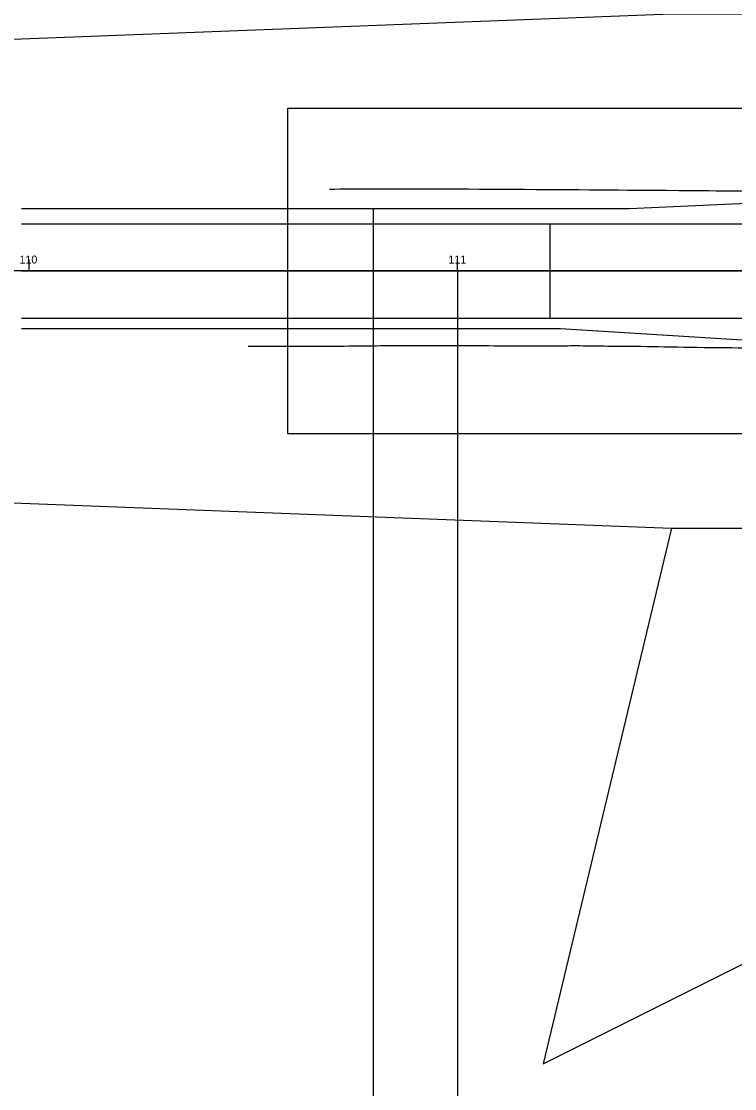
# Model space of a CAD drawing. Extents: x -1300 to 1299, y -770 to 1120.
# Drawn here: x 391.5 to 558, y 234.1 to 483.1 of the extents above; entities that cross this region are included whole.
import ezdxf

# ---------------------------------------------------------------- set-up
doc = ezdxf.new("R2010")
doc.units = 0
for name, color, linetype in [('GE_X_CL_20', 7, 'Continuous'), ('MD_P_CONST_LIMITS', 7, 'Continuous'), ('PM_P_CL_Dashed', 7, 'Continuous'), ('PM_X_CL_Dashed', 7, 'Continuous'), ('PM_X_Edge_Line', 7, 'Continuous'), ('PV_P_Shoulder_Rumble_Strip', 7, 'Continuous'), ('PV_X_EOP', 7, 'Continuous'), ('RD_X_GR_Lt', 7, 'Continuous'), ('RD_X_GR_Rt', 7, 'Continuous'), ('RW_X_Esmt_CH', 7, 'Continuous'), ('RW_X_Fee_RW', 7, 'Continuous'), ('SC_Scratch1', 7, 'Continuous'), ('SC_Scratch2', 7, 'Continuous')]:
    doc.layers.add(name, color=color, linetype=linetype)

msp = doc.modelspace()

# ---------------------------------------------------------------- linework, layer by layer
at = {"layer": 'GE_X_CL_20'}
for p, q in [((393.26, 424.91), (393.26, 426.24)), ((493.26, 424.91), (493.26, 426.24)), ((391.46, 424.91), (920.48, 424.91))]:
    msp.add_line(p, q, dxfattribs=at)
at = {"layer": 'MD_P_CONST_LIMITS'}
msp.add_lwpolyline([(453.64, 462.91), (867.88, 462.91), (867.88, 386.91), (453.64, 386.91)], close=True, dxfattribs=at)
at = {"layer": 'PM_P_CL_Dashed'}
msp.add_line((473.64, 424.91), (847.88, 424.91), dxfattribs=at)
at = {"layer": 'PM_X_CL_Dashed'}
msp.add_line((473.64, 424.91), (151.14, 424.91), dxfattribs=at)
at = {"layer": 'PM_X_Edge_Line'}
for p, q in [((391.46, 435.91), (920.48, 435.91)), ((391.46, 413.91), (920.48, 413.91))]:
    msp.add_line(p, q, dxfattribs=at)
at = {"layer": 'PV_P_Shoulder_Rumble_Strip'}
msp.add_line((611.14, 424.91), (193.26, 424.91), dxfattribs=at)
at = {"layer": 'PV_X_EOP'}
for points in [[(621.54, 442.91), (610.47, 442.91), (533.45, 439.41), (391.46, 439.41)], [(600.75, 406.91), (589.69, 406.91), (517.28, 411.41), (391.46, 411.41)]]:
    msp.add_lwpolyline(points, dxfattribs=at)
at = {"layer": 'RD_X_GR_Lt'}
msp.add_open_spline([(596, 406.91), (587.6, 406.9), (581.57, 406.91), (574.81, 406.91), (569.65, 406.78), (559.34, 406.93), (545.66, 407.05), (534.45, 407.31), (526.08, 407.31), (520.46, 407.46), (514.42, 407.28), (505.23, 407.39), (481.4, 407.51), (469.35, 407.3), (451.19, 407.23), (444.37, 407.31)], degree=3, dxfattribs=at)
at = {"layer": 'RD_X_GR_Rt'}
msp.add_open_spline([(616.46, 442.92), (603.16, 442.96), (595.89, 442.89), (588.44, 443.03), (575.12, 443.26), (561.63, 443.48), (552.94, 443.56), (475.29, 444.16), (463.39, 443.93)], degree=3, dxfattribs=at)
at = {"layer": 'RW_X_Esmt_CH'}
msp.add_lwpolyline([(543.26, 364.91), (513.26, 239.91), (593.26, 279.91), (698.26, 364.91)], dxfattribs=at)
at = {"layer": 'RW_X_Fee_RW'}
for points in [[(193.26, 471.45), (543.26, 484.91), (763.26, 484.91), (1043.26, 474.91)], [(193.26, 378.37), (543.26, 364.91), (763.26, 364.91), (1043.26, 379.91)]]:
    msp.add_lwpolyline(points, dxfattribs=at)
at = {"layer": 'SC_Scratch1'}
for p, q in [((473.64, -369.36), (473.64, 439.41)), ((514.91, 424.91), (514.91, 435.91)), ((393.26, 426.24), (393.26, 427.58)), ((493.26, 426.24), (493.26, 427.58)), ((391.46, 424.91), (193.26, 424.91)), ((514.91, 413.91), (514.91, 424.91))]:
    msp.add_line(p, q, dxfattribs=at)
at = {"layer": 'SC_Scratch2'}
msp.add_line((493.26, 424.91), (493.26, -375.93), dxfattribs=at)

# ---------------------------------------------------------------- texts
at = {"layer": 'GE_X_CL_20'}
for s, p in [('110', (391.03, 426.64)), ('111', (491.16, 426.64))]:
    msp.add_text(s, height=1.867, dxfattribs=at).set_placement(p)

doc.saveas('drawing.dxf')
